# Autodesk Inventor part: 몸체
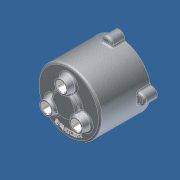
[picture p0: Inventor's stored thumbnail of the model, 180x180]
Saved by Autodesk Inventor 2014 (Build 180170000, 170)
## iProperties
Created: 2012-05
Part Number: 몸체
Document SubType Name: 모델링
Designer: SeoGD™
Material: 일반
Appearance: 기본값
Mass: 175.481 g
Surface Area: 687.661 cm^2
Volume: 175.481 cm^3
Density: 1 g/cm^3
변환 표준: STEP AP214IS
파일 이름: C:\Users\SeoGD\Desktop\?쒗뿕\紐몄껜.stp
전처리기: Build: 253, Release: 2010 SP1 - Date: Wed 07/29/2009
전송 단위: 밀리미터
불확실성: 0.01
Author: SeoGD™
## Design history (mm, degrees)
sketch "스케치2"
  geometry: C1 r 50 at (0, 0); 1 further point
  constraints: 1 centre point, 1 coincident
  dimensions: "d9" = 100 diameter of C1
extrude "돌출2" new body sketch "스케치2" distance "d10" = 80; taper "d11" = 0 deg
feature "쉘1" dims "d12" = 5
sketch "스케치3" dims "d13" = 55
  geometry: C1 r 7.5 at (0, 27.5); C2 r 12.5 at (0, 27.5); 2 further points
  constraints: 2 centre point, 2 coincident, 2 vertical alignment, 2 other
  dimensions: "d14" = 15 diameter of C1; "d15" = 25 diameter of C2
extrude "돌출3" join sketch "스케치3" distance "d16" = 12; taper "d17" = -10 deg
hole "구멍2" diameter "d20" = 15; stored, may be unused: countersink angle "d24" = 90 deg, drill point angle "d26" = 118 deg; dims "d18" = 10, "d19" = 10, "d21" = 6, "d22" = 4, "d23" = 2, "d25" = 15
chamfer "모따기1" distance "d27" = 1; stored, may be unused: second distance "d28" = 2, angle "d29" = 45 deg
sketch "스케치4"
  geometry: L1 (0, 0)-(0, 88); L2 (0, 70)-(13.16, 70); L3 (-45, 75)-(45, 75) reference; L4 (-50, 80)-(50, 80) reference; L5 (13.16, 70)-(14.5, 75); L6 (20, 80)-(20, 88); L7 (20, 88)-(0, 88); L8 (20, 80)-(14.5, 75)
  constraints: 12 end point, 3 point on line, 2 perpendicular, 1 vertical
  dimensions: "d34" = 40 diameter of L6 L1; "d35" = 105 deg angle of L5 L3; "d36" = 5 distance between parallel lines of L2 L3; "d37" = 8 distance between parallel lines of L7 L4; "d51" = 29 diameter of L5.end L1
revolve "회전1" sketch "스케치4" stored, may be unused: angle "d38" = 90 deg
hole "구멍3" diameter "d41" = 15; stored, may be unused: countersink angle "d45" = 90 deg, drill point angle "d47" = 0 deg; dims "d39" = 10, "d40" = 10, "d42" = 6, "d43" = 22, "d44" = 13, "d46" = 15
chamfer "모따기2" distance "d48" = 1; stored, may be unused: second distance "d49" = 2, angle "d50" = 45 deg
fillet "모깎기1" dims "d52" = 3
fillet "모깎기2" dims "d53" = 3, "d72" = 0.2
sketch "스케치5"
  geometry: A1 r 50 centre (0, 0) between (50, 0) and (-8.074, 49.344) reference; A2 r 8.5 centre (0, 52) between (8.074, 49.344) and (-8.074, 49.344); 1 further point
  constraints: 5 point on circle, 1 centre point, 1 horizontal alignment
  dimensions: "d54" = 90 deg dimension on point (0, 0) A2.centre A1.start; "d55" = 52 distance of A2.centre point (0, 0); "d56" = 17 diameter of A2
extrude "돌출4" join sketch "스케치5" distance "d57" = 20; taper "d58" = 0 deg
fillet "모깎기3" dims "d59" = 3
hole "구멍4" diameter "d62" = 4.134; stored, may be unused: countersink angle "d66" = 90 deg, drill point angle "d68" = 118 deg; dims "d60" = 10, "d61" = 10, "d63" = 12, "d64" = 22, "d65" = 13, "d67" = 15
sketch "스케치6"
  geometry: C1 r 47 at (0, 0) reference; C2 r 42.5 at (0, 0); 1 further point
  constraints: 1 centre point, 1 coincident, 1 other
  dimensions: "d73" = 85 diameter of C2
feature "엠보싱1" sketch "스케치6" dims "d74" = 1, "d75" = 0
node "솔리드1"
node "솔리드 본체"
node "곡면 본체"
pattern_circular "원형 패턴1" dims "d31" = 360 deg
pattern_circular "원형 패턴2" dims "d70" = 360 deg
node "솔리드2"
